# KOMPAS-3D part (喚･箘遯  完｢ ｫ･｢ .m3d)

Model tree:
1. Эскиз:1
2. Операция выдавливания:1
     Расстояние 1 = 2
3. Фаска:3
     Угол = 25; Длина 1 = 3; Длина 2 = 1.39892
4. Эскиз:2
5. Операция выдавливания:2
     Расстояние 1 = 64
6. Скругление:1
     Радиус = 1
7. Скругление:2
     Радиус = 3
8. Эскиз:3
9. Вырезать элемент выдавливания:2
     Расстояние 2 = 62; Расстояние 1 = 40
10. Скругление:3
     Радиус = 1
11. Эскиз:4
12. Вырезать элемент выдавливания:3
     Расстояние 2 = 64; Расстояние 1 = 40
13. Скругление:4
     Радиус = 0.5
14. Эскиз:5
15. Вырезать элемент выдавливания:4
     Расстояние 2 = 20; Расстояние 1 = 20
16. Скругление:5
     Радиус = 0.5
17. Скругление:6
     Радиус = 0.5
18. Эскиз:6
19. Вырезать элемент выдавливания:5
     Расстояние 2 = 7; Расстояние 1 = 7
20. Скругление:7
     Радиус = 0.5
21. Скругление:8
     Радиус = 0.5
22. Эскиз:7
23. Вырезать элемент выдавливания:6
     Расстояние 2 = 20; Расстояние 1 = 30
24. Эскиз:8
25. Операция выдавливания:3
     Расстояние 1 = 20; Расстояние 2 = 35
26. Эскиз:9
27. Операция выдавливания:4
     Расстояние 1 = 3; Расстояние 2 = 5
28. Фаска:5
     Угол = 45; Длина 1 = 2; Длина 2 = 2
29. Фаска:6
     Угол = 45; Длина 1 = 2; Длина 2 = 2
30. Скругление:9
     Радиус = 0.3
31. Скругление:10
     Радиус = 0.5
